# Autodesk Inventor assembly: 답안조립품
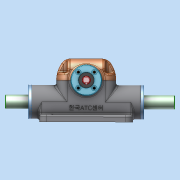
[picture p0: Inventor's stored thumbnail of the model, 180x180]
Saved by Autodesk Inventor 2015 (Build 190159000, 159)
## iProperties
Created: 2024-06
Part Number: 답안조립품
Document SubType Name: Assembly
Designer: Administrator
Author: Administrator
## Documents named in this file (11)
- C:\Users\Administrator\Desktop\740604V1012\답안조립품.iam
- C:\Users\Administrator\Desktop\740604V1012\본체.ipt
- C:\Users\Administrator\Desktop\740604V1012\랙.ipt
- C:\Users\Administrator\Desktop\740604V1012\칼라.ipt
- C:\Users\Administrator\Desktop\740604V1012\피니언.ipt
- C:\Users\Administrator\Desktop\740604V1012\깊은 홈 볼 베어링 6901.ipt
- C:\Users\Administrator\Desktop\740604V1012\윗커버.ipt
- C:\Users\Administrator\Desktop\740604V1012\베어링 커버.ipt
- C:\Users\Administrator\Desktop\740604V1012\오일실 12 22 7.ipt
- C:\Users\Administrator\Desktop\740604V1012\오일레스 부시.ipt
- C:\Users\Administrator\Desktop\740604V1012\부시 커버.ipt
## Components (1 placed, 1 different names)
1. 피니언:1
